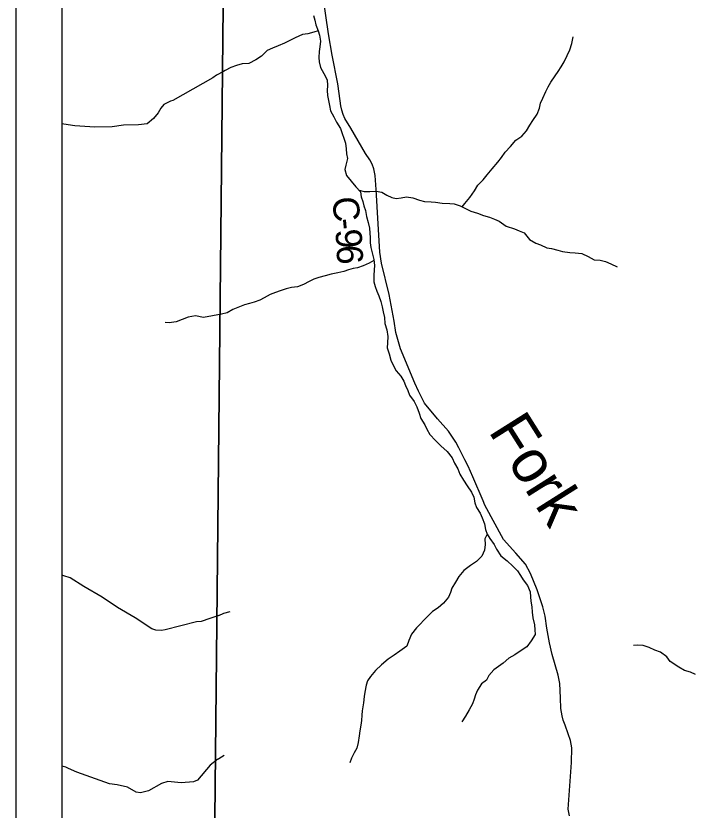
# Model space of a CAD drawing. Extents: x 0 to 34, y 0 to 22.
# Drawn here: x 2 to 3.475, y 15.178 to 16.905 of the extents above; entities that cross this region are included whole.
import ezdxf

# ---------------------------------------------------------------- set-up
doc = ezdxf.new("R2010")
doc.units = 0
for name, color, linetype in [('Default', 7, 'Continuous'), ('GM_X_County_Road', 7, 'Continuous'), ('GM_X_County_Road_Text', 7, 'Continuous'), ('GM_X_Minor_River', 7, 'Continuous'), ('GM_X_Minor_River_Text', 7, 'Continuous'), ('SH_Cut_Line', 7, 'Continuous'), ('SH_Data', 7, 'Continuous')]:
    doc.layers.add(name, color=color, linetype=linetype)

msp = doc.modelspace()

# ---------------------------------------------------------------- linework, layer by layer
at = {"layer": 'Default'}
for points in [[(2.4313, 15.0183), (2.4545, 17.2795), (2.4586, 17.7785), (2.4581, 18.1772), (2.4581, 18.1825), (2.4573, 18.9074), (2.4757, 20.2566), (2.4809, 20.6393), (2.4845, 20.9), (2.1, 20.9), (2.1, 14.9328)], [(3.5442, 17.5398), (3.4629, 17.4891), (3.467, 17.2465), (3.4366, 17.255), (2.6193, 17.2753), (2.4545, 17.2795), (2.4313, 15.0183)]]:
    msp.add_lwpolyline(points, dxfattribs=at)
at = {"layer": 'GM_X_County_Road'}
msp.add_lwpolyline([(3.2043, 15.1658), (3.2013, 15.1804), (3.2085, 15.2817), (3.209, 15.3132), (3.2067, 15.3291), (3.2017, 15.3436), (3.1945, 15.363), (3.1906, 15.3735), (3.1885, 15.3828), (3.1857, 15.3987), (3.1845, 15.4223), (3.1829, 15.4534), (3.1795, 15.4713), (3.1669, 15.5164), (3.1604, 15.5419), (3.1552, 15.5734), (3.1512, 15.5998), (3.1459, 15.6198), (3.1339, 15.6573), (3.1194, 15.6923), (3.1084, 15.7129), (3.0873, 15.7368), (3.0607, 15.766), (3.0204, 15.841), (3.0163, 15.8505), (2.9937, 15.9027), (2.9835, 15.9258), (2.9766, 15.9392), (2.9634, 15.9658), (2.957, 15.978), (2.9411, 16.002), (2.9174, 16.0284), (2.8885, 16.0626), (2.8758, 16.089), (2.8677, 16.1061), (2.8364, 16.1808), (2.8265, 16.2163), (2.823, 16.2407), (2.8121, 16.2988), (2.7956, 16.3669), (2.7919, 16.3906), (2.7879, 16.4525), (2.7836, 16.5273), (2.7816, 16.5575), (2.7784, 16.5723), (2.775, 16.5825), (2.7699, 16.5918), (2.7607, 16.6055), (2.7284, 16.6602), (2.7154, 16.6816), (2.7117, 16.6904), (2.7091, 16.6996), (2.7069, 16.7087), (2.7054, 16.72), (2.7003, 16.7566), (2.6882, 16.8195), (2.6801, 16.8655), (2.6677, 16.9508)], dxfattribs=at)
at = {"layer": 'GM_X_Minor_River'}
for points in [[(2.6474, 16.9055), (2.65, 16.8956), (2.6522, 16.885), (2.6578, 16.8724), (2.6604, 16.8629), (2.6625, 16.8496), (2.6613, 16.8374), (2.6597, 16.8268), (2.6592, 16.8143), (2.6599, 16.8044), (2.6625, 16.7922), (2.67, 16.7793), (2.6771, 16.7656), (2.6778, 16.7534), (2.6773, 16.7424), (2.6776, 16.7314), (2.682, 16.7101), (2.6842, 16.6983), (2.6913, 16.6853), (2.6973, 16.6735), (2.7059, 16.6598), (2.71, 16.6487), (2.7137, 16.6385), (2.7167, 16.6278), (2.7181, 16.6153), (2.7191, 16.605), (2.7213, 16.5943), (2.7178, 16.5799), (2.7158, 16.5705), (2.7195, 16.5575)], [(2.6579, 16.872), (2.6479, 16.8691), (2.6353, 16.8657), (2.6236, 16.8639), (2.6072, 16.8568), (2.5973, 16.8519), (2.5843, 16.8452), (2.5706, 16.8392), (2.5581, 16.8344), (2.5463, 16.8291), (2.5344, 16.8167), (2.5218, 16.8088), (2.5066, 16.8013), (2.4925, 16.8006), (2.48, 16.7969), (2.4674, 16.7924), (2.4549, 16.7857), (2.4513, 16.7834)], [(2.971, 16.4896), (2.9767, 16.4965), (2.9875, 16.5097), (2.9974, 16.5245), (3.0051, 16.5366), (3.0166, 16.5483), (3.0254, 16.5588), (3.0361, 16.5724), (3.048, 16.5864), (3.056, 16.597), (3.0641, 16.608), (3.0756, 16.6208), (3.0878, 16.6344), (3.1004, 16.6434), (3.1104, 16.6547), (3.1177, 16.6668), (3.1246, 16.677), (3.1338, 16.691), (3.1388, 16.7039), (3.1412, 16.7145), (3.1462, 16.7259), (3.1531, 16.7399), (3.1578, 16.7505), (3.1639, 16.7607), (3.1731, 16.7739), (3.1793, 16.7838), (3.1862, 16.7936), (3.1923, 16.805), (3.1989, 16.8182), (3.2047, 16.8311), (3.2093, 16.8447), (3.2125, 16.8587)], [(2.4513, 16.7834), (2.4364, 16.7756), (2.4284, 16.7696), (2.3414, 16.7208), (2.3361, 16.7193), (2.322, 16.7118), (2.3151, 16.7042), (2.3094, 16.6936), (2.2995, 16.6812), (2.2854, 16.6702), (2.2668, 16.6677), (2.2342, 16.6667), (2.2096, 16.6634), (2.1717, 16.6625), (2.1286, 16.6658), (2.1229, 16.6662), (2.1, 16.6699)], [(2.7195, 16.5575), (2.7293, 16.5453), (2.7398, 16.5331), (2.7496, 16.5224), (2.7514, 16.511), (2.7544, 16.5011), (2.757, 16.4916), (2.7607, 16.4813), (2.7625, 16.4687), (2.7666, 16.4558), (2.7691, 16.4429), (2.7702, 16.4326), (2.7705, 16.4227), (2.7708, 16.4109), (2.7719, 16.4011), (2.7756, 16.3866), (2.7785, 16.3748), (2.7803, 16.3623), (2.7795, 16.3524), (2.7786, 16.3402), (2.7789, 16.3266), (2.7815, 16.3163), (2.7852, 16.306), (2.7897, 16.2961), (2.7938, 16.2839), (2.7967, 16.2721), (2.7989, 16.2611), (2.8015, 16.2486), (2.8029, 16.2356), (2.807, 16.2219), (2.8091, 16.2079), (2.8083, 16.1942), (2.8078, 16.1832), (2.8123, 16.1699), (2.8159, 16.1562), (2.8197, 16.1467), (2.8275, 16.1333), (2.8373, 16.1211), (2.8441, 16.1104), (2.8478, 16.1009), (2.8523, 16.0902), (2.8564, 16.0803), (2.8661, 16.0662), (2.8725, 16.0551), (2.8769, 16.0411), (2.8806, 16.0293), (2.8893, 16.0159), (2.8938, 16.0064), (2.9005, 15.9949), (2.9125, 15.9819), (2.9246, 15.9701), (2.9378, 15.9578), (2.9491, 15.9441), (2.9539, 15.9323), (2.9614, 15.9197), (2.9659, 15.9087), (2.9737, 15.8953), (2.982, 15.8831), (2.991, 15.869), (2.9959, 15.8583), (2.9984, 15.8462), (3.0018, 15.8359), (3.0096, 15.8237), (3.0145, 15.8138), (3.0193, 15.8004), (3.0215, 15.7883), (3.0252, 15.778), (3.0312, 15.7685), (3.0402, 15.7555), (3.0451, 15.7452), (3.0552, 15.7311), (3.0684, 15.72), (3.0812, 15.7085), (3.0914, 15.6982), (3.0974, 15.6882), (3.1034, 15.6787), (3.1132, 15.6661), (3.1188, 15.6528), (3.1191, 15.6418), (3.1201, 15.6323), (3.1223, 15.6197), (3.123, 15.6083), (3.1248, 15.5958), (3.1281, 15.5806), (3.1292, 15.5699), (3.1295, 15.56), (3.121, 15.546), (3.1118, 15.5332), (3.0992, 15.5253), (3.0851, 15.5159), (3.0722, 15.5084), (3.0603, 15.4978), (3.0496, 15.4903), (3.0397, 15.4832), (3.029, 15.4707), (3.0236, 15.4605), (3.0129, 15.4526), (3.0041, 15.4386), (2.9998, 15.4288), (2.9967, 15.4193), (2.9929, 15.4094)], [(2.7469, 16.5254), (2.7576, 16.5231), (2.7701, 16.5226), (2.7834, 16.5237), (2.7963, 16.5213), (2.8069, 16.5151), (2.8175, 16.5098), (2.8273, 16.5078), (2.8383, 16.5088), (2.8497, 16.5111), (2.8634, 16.5091), (2.8778, 16.504), (2.8887, 16.5013), (2.9032, 16.5004), (2.913, 16.4996), (2.927, 16.4976), (2.9441, 16.4967), (2.9536, 16.4963), (2.9661, 16.492), (2.9793, 16.4855), (2.9899, 16.4801), (3.0043, 16.4754), (3.0175, 16.4704), (3.0304, 16.4669), (3.041, 16.463), (3.0516, 16.458), (3.0663, 16.4473), (3.0849, 16.4418), (3.0951, 16.4376), (3.1053, 16.433), (3.1169, 16.4188), (3.1313, 16.4104), (3.1411, 16.4069), (3.1551, 16.4007), (3.165, 16.3988), (3.1786, 16.3956), (3.1888, 16.3925), (3.2051, 16.3905), (3.2165, 16.3897), (3.2313, 16.388), (3.2449, 16.3815), (3.2578, 16.3746), (3.271, 16.3733), (3.2828, 16.371), (3.2941, 16.3656), (3.3077, 16.359)], [(2.7788, 16.3726), (2.7686, 16.3673), (2.7556, 16.3609), (2.7431, 16.3572), (2.7336, 16.3557), (2.7237, 16.3528), (2.7134, 16.349), (2.7005, 16.3457), (2.6861, 16.3432), (2.6727, 16.3395), (2.6591, 16.3361), (2.6484, 16.332), (2.6377, 16.3272), (2.6259, 16.3204), (2.6126, 16.3159), (2.5993, 16.3141), (2.5883, 16.3112), (2.5746, 16.3067), (2.5647, 16.3033), (2.5533, 16.2989), (2.5403, 16.2914), (2.5304, 16.2869), (2.5186, 16.282), (2.5084, 16.2794), (2.4973, 16.2768), (2.4867, 16.2724), (2.4718, 16.266), (2.4593, 16.2593), (2.447, 16.2559)], [(2.447, 16.2559), (2.4078, 16.2492), (2.3908, 16.2523), (2.3745, 16.2494), (2.349, 16.2393), (2.3331, 16.2375), (2.3244, 16.2383)], [(3.0252, 15.778), (3.0202, 15.7678), (3.0205, 15.7556), (3.0197, 15.7435), (3.0139, 15.7302), (3.0016, 15.7185), (2.9887, 15.7095), (2.9745, 15.6993), (2.9634, 15.6861), (2.9561, 15.6736), (2.9485, 15.6608), (2.9453, 15.6509), (2.9411, 15.6411), (2.93, 15.6282), (2.9189, 15.6181), (2.9063, 15.6102), (2.8956, 15.5989), (2.8711, 15.574), (2.8604, 15.5604), (2.8546, 15.5467), (2.8504, 15.5346), (2.8355, 15.5237), (2.8229, 15.515), (2.8099, 15.5064), (2.795, 15.4936), (2.7824, 15.4815), (2.7713, 15.4687), (2.7648, 15.4588), (2.7617, 15.4494), (2.7589, 15.4346), (2.7577, 15.4251), (2.7565, 15.411), (2.7529, 15.394), (2.7525, 15.3845), (2.752, 15.3731), (2.75, 15.3625), (2.7484, 15.3507), (2.7464, 15.3397), (2.7448, 15.3253), (2.7413, 15.3124), (2.7355, 15.3026), (2.7298, 15.2908), (2.7266, 15.2806)], [(2.4417, 15.6014), (2.422, 15.5947), (2.403, 15.5879), (2.3932, 15.5876), (2.3249, 15.5701), (2.3166, 15.5683), (2.3041, 15.5695), (2.2954, 15.5722), (2.2592, 15.5963), (2.2214, 15.6185), (2.1879, 15.6411), (2.1475, 15.6645), (2.1184, 15.6828), (2.1045, 15.6874), (2.1, 15.6886)], [(2.4417, 15.6014), (2.4525, 15.6061), (2.4658, 15.6098)], [(3.4231, 15.5008), (3.4158, 15.5111), (3.4024, 15.5217), (3.3899, 15.5256), (3.3774, 15.5314), (3.3645, 15.536), (3.3532, 15.5365), (3.3437, 15.5358)], [(3.478, 15.473), (3.4674, 15.478), (3.4545, 15.4814), (3.442, 15.4891), (3.4231, 15.5008)], [(2.9929, 15.4094), (2.9863, 15.3958), (2.9782, 15.3826), (2.9702, 15.3701)], [(2.4391, 15.2886), (2.4414, 15.2905), (2.4532, 15.2977)], [(2.4391, 15.2886), (2.4223, 15.276), (2.3949, 15.2431), (2.3865, 15.2394), (2.3592, 15.2372), (2.3305, 15.24), (2.3168, 15.2363), (2.2887, 15.2198), (2.2709, 15.2157), (2.2618, 15.2173), (2.2429, 15.228), (2.2202, 15.2331), (2.2039, 15.235), (2.1329, 15.2605), (2.1144, 15.2689), (2.1087, 15.2712), (2.1, 15.2734)]]:
    msp.add_lwpolyline(points, dxfattribs=at)
at = {"layer": 'SH_Cut_Line'}
for points in [[(2.4845, 20.9), (2.1, 20.9), (2.1, 14.1), (2.4352, 14.1), (2.4372, 14.2719), (2.4313, 15.0183), (2.4545, 17.2795), (2.4586, 17.7785), (2.4581, 18.1772), (2.4581, 18.1825), (2.4573, 18.9074), (2.4757, 20.2566), (2.4809, 20.6393)], [(2.4352, 14.1), (8.9, 14.1), (8.9, 20.9), (2.4845, 20.9), (2.4809, 20.6393), (2.4757, 20.2566), (2.4573, 18.9074), (2.4581, 18.1825), (2.4581, 18.1772), (2.4586, 17.7785), (2.4545, 17.2795), (2.4313, 15.0183), (2.4372, 14.2719)]]:
    msp.add_lwpolyline(points, close=True, dxfattribs=at)
at = {"layer": 'SH_Data'}
for p, q in [((2, 21), (2, 14)), ((2.1, 20.9), (2.1, 14.1))]:
    msp.add_line(p, q, dxfattribs=at)

# ---------------------------------------------------------------- texts
at = {"layer": 'GM_X_County_Road_Text'}
for s, rotation, p in [('C', 276.0904, (2.6877, 16.5089)), ('-', 275.3195, (2.6926, 16.4627)), ('9', 273.7886, (2.6948, 16.4398)), ('6', 272.793, (2.6971, 16.4052))]:
    msp.add_text(s, height=0.0568, rotation=rotation, dxfattribs=at).set_placement(p)
at = {"layer": 'GM_X_Minor_River_Text'}
msp.add_text('Fork', height=0.0947, rotation=302.2395, dxfattribs=at).set_placement((3.0265, 16.0021))

doc.saveas('drawing.dxf')
